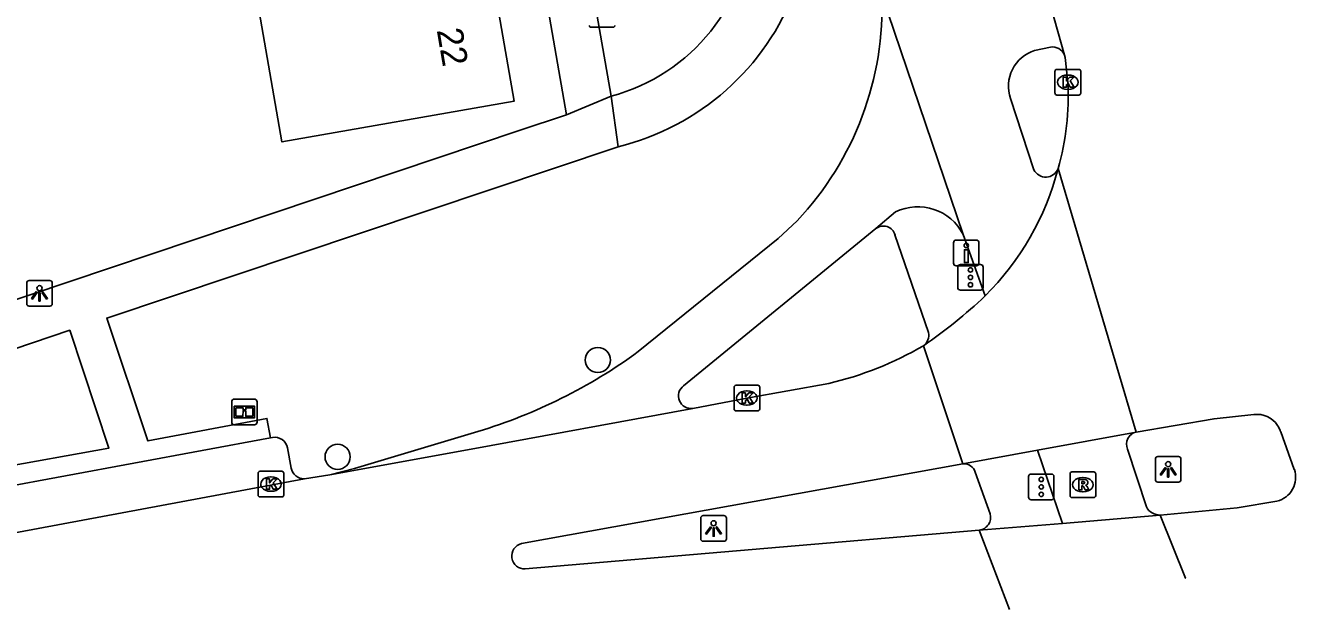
# Model space of a CAD drawing. Extents: x 160158 to 160921, y 381517 to 382041.
# Drawn here: x 160482.63 to 160532.12, y 381526.49 to 381549.26 of the extents above; entities that cross this region are included whole.
import ezdxf

# ---------------------------------------------------------------- set-up
doc = ezdxf.new("R2010")
doc.units = 0
for name, color, linetype in [('IMGEO_Boom', 7, 'Continuous'), ('IMGEO_Drukknoppaal', 7, 'Continuous'), ('IMGEO_Fietspad_gesloten', 7, 'Continuous'), ('IMGEO_Informatiebord', 7, 'Continuous'), ('IMGEO_Kolk', 7, 'Continuous'), ('IMGEO_Lichtpunt', 7, 'Continuous'), ('IMGEO_Pand', 7, 'Continuous'), ('IMGEO_Pand_nummerreeks', 7, 'Continuous'), ('IMGEO_Parkeervlak_open', 7, 'Continuous'), ('IMGEO_Rijbaan_lokaal_gesloten', 7, 'Continuous'), ('IMGEO_Rijbaan_regionaal_gesloten', 7, 'Continuous'), ('IMGEO_Rioolput', 7, 'Continuous'), ('IMGEO_Verkeersregelinstallatiepaal', 7, 'Continuous'), ('IMGEO_Voetpad_open', 7, 'Continuous')]:
    doc.layers.add(name, color=color, linetype=linetype)

msp = doc.modelspace()

# ---------------------------------------------------------------- linework, layer by layer
at = {"layer": 'IMGEO_Boom'}
for centre in [(160504.935, 381536.218), (160494.795, 381532.443)]:
    msp.add_circle(centre, 0.489, dxfattribs=at)
at = {"layer": 'IMGEO_Drukknoppaal'}
for p, q in [((160518.794, 381539.992), (160518.794, 381540.792)), ((160518.794, 381540.792), (160518.794, 381539.992)), ((160518.894, 381540.892), (160519.684, 381540.892)), ((160519.684, 381540.892), (160518.894, 381540.892)), ((160519.784, 381540.792), (160519.784, 381539.992)), ((160519.784, 381539.992), (160519.784, 381540.792)), ((160519.684, 381539.892), (160518.894, 381539.892)), ((160518.894, 381539.892), (160519.684, 381539.892))]:
    msp.add_line(p, q, dxfattribs=at)
msp.add_lwpolyline([(160519.364, 381540.517), (160519.364, 381540.017), (160519.214, 381540.017), (160519.214, 381540.517), (160519.364, 381540.517)], dxfattribs=at)
msp.add_circle((160519.289, 381540.682), 0.085, dxfattribs=at)
for centre, start, end in [((160518.894, 381540.792), 90, 180), ((160518.894, 381540.792), 90, 180), ((160519.684, 381540.792), 0, 90), ((160519.684, 381540.792), 360, 90), ((160518.894, 381539.992), 180, 270), ((160518.894, 381539.992), 180, 270), ((160519.684, 381539.992), 270, 0), ((160519.684, 381539.992), 270, 0)]:
    msp.add_arc(centre, 0.1, start, end, dxfattribs=at)
at = {"layer": 'IMGEO_Fietspad_gesloten'}
for points in [[(160515.994, 381550.461), (160519.169, 381541.105)], [(160521.952, 381548.285), (160522.568, 381548.415)], [(160521.927, 381543.633), (160521.008, 381546.411)], [(160515.762, 381541.343), (160516.531, 381541.99)], [(160512.701, 381541.648), (160511.966, 381540.956), (160506.509, 381536.545)], [(160508.278, 381535.212), (160515.762, 381541.343)], [(160519.169, 381541.105), (160520.02, 381538.714)], [(160500.264, 381533.433), (160495.449, 381531.994), (160494.487, 381531.742)], [(160522.061, 381532.706), (160523.041, 381529.844)], [(160525.573, 381532.737), (160526.311, 381530.488)]]:
    msp.add_lwpolyline(points, dxfattribs=at)
for centre, radius, start, end in [((160503.878, 381549.967), 12.126, 316.6864, 2.3369), ((160522.652, 381547.922), 0.5, 21.5779, 99.6769), ((160522.404, 381546.882), 1.474, 107.8788, 198.6492), ((160522.387, 381543.858), 0.512, 206.0086, 339.4729), ((160517.403, 381540.215), 1.977, 26.7399, 116.1688), ((160494.294, 381553.235), 20.682, 286.7768, 306.1991), ((160508.562, 381534.816), 0.488, 125.6155, 279.0857), ((160526.027, 381532.931), 0.494, 103.4475, 203.1507), ((160526.835, 381530.767), 0.594, 207.982, 271.1336)]:
    msp.add_arc(centre, radius, start, end, dxfattribs=at)
at = {"layer": 'IMGEO_Informatiebord'}
for p, q in [((160490.668, 381533.793), (160490.668, 381534.593)), ((160490.668, 381534.593), (160490.668, 381533.793)), ((160490.768, 381534.693), (160491.558, 381534.693)), ((160491.558, 381534.693), (160490.768, 381534.693)), ((160491.658, 381534.593), (160491.658, 381533.793)), ((160491.658, 381533.793), (160491.658, 381534.593)), ((160491.558, 381533.693), (160490.768, 381533.693)), ((160490.768, 381533.693), (160491.558, 381533.693))]:
    msp.add_line(p, q, dxfattribs=at)
for points in [[(160490.769, 381534.425), (160491.557, 381534.425), (160491.557, 381533.961), (160490.769, 381533.961), (160490.769, 381534.425)], [(160490.834, 381534.36), (160490.834, 381534.026), (160491.109, 381534.026), (160491.11, 381534.239), (160491.214, 381534.24), (160491.215, 381534.026), (160491.492, 381534.026), (160491.492, 381534.36), (160491.216, 381534.36), (160491.216, 381534.28), (160491.11, 381534.28), (160491.11, 381534.36), (160490.834, 381534.36)]]:
    msp.add_lwpolyline(points, dxfattribs=at)
for centre, start, end in [((160490.768, 381534.593), 90, 180), ((160490.768, 381534.593), 90, 180), ((160491.558, 381534.593), 0, 90), ((160491.558, 381534.593), 360, 90), ((160490.768, 381533.793), 180, 270), ((160490.768, 381533.793), 180, 270), ((160491.558, 381533.793), 270, 0), ((160491.558, 381533.793), 270, 0)]:
    msp.add_arc(centre, 0.1, start, end, dxfattribs=at)
at = {"layer": 'IMGEO_Kolk'}
for p, q in [((160522.746, 381546.622), (160522.746, 381547.474)), ((160522.821, 381547.548), (160523.673, 381547.548)), ((160523.747, 381547.474), (160523.747, 381546.622)), ((160523.234, 381547.328), (160523.259, 381547.328)), ((160523.673, 381546.548), (160522.821, 381546.548)), ((160523.257, 381546.768), (160523.232, 381546.768)), ((160510.243, 381534.31), (160510.243, 381535.162)), ((160510.318, 381535.236), (160511.17, 381535.236)), ((160510.731, 381535.016), (160510.756, 381535.016)), ((160511.244, 381535.162), (160511.244, 381534.31)), ((160511.17, 381534.236), (160510.318, 381534.236)), ((160510.754, 381534.456), (160510.729, 381534.456)), ((160491.698, 381530.954), (160491.698, 381531.806)), ((160491.773, 381531.88), (160492.625, 381531.88)), ((160492.186, 381531.66), (160492.211, 381531.66)), ((160492.699, 381531.806), (160492.699, 381530.954)), ((160492.209, 381531.1), (160492.184, 381531.1)), ((160492.625, 381530.88), (160491.773, 381530.88))]:
    msp.add_line(p, q, dxfattribs=at)
for points in [[(160522.746, 381546.622), (160522.746, 381547.474)], [(160522.821, 381547.548), (160523.673, 381547.548)], [(160523.747, 381547.474), (160523.747, 381546.622)], [(160523.067, 381547.248), (160523.19, 381547.248), (160523.19, 381547.097), (160523.32, 381547.248), (160523.484, 381547.248), (160523.338, 381547.097), (160523.491, 381546.848), (160523.339, 381546.848), (160523.254, 381547.012), (160523.19, 381546.945), (160523.19, 381546.848), (160523.067, 381546.848), (160523.067, 381547.248)], [(160523.673, 381546.548), (160522.821, 381546.548)], [(160510.243, 381534.31), (160510.243, 381535.162)], [(160510.318, 381535.236), (160511.17, 381535.236)], [(160511.244, 381535.162), (160511.244, 381534.31)], [(160510.564, 381534.936), (160510.687, 381534.936), (160510.687, 381534.785), (160510.817, 381534.936), (160510.981, 381534.936), (160510.835, 381534.785), (160510.988, 381534.536), (160510.836, 381534.536), (160510.751, 381534.7), (160510.687, 381534.633), (160510.687, 381534.536), (160510.564, 381534.536), (160510.564, 381534.936)], [(160511.17, 381534.236), (160510.318, 381534.236)], [(160491.698, 381530.954), (160491.698, 381531.806)], [(160491.773, 381531.88), (160492.625, 381531.88)], [(160492.019, 381531.58), (160492.142, 381531.58), (160492.142, 381531.429), (160492.272, 381531.58), (160492.436, 381531.58), (160492.29, 381531.429), (160492.443, 381531.18), (160492.291, 381531.18), (160492.206, 381531.344), (160492.142, 381531.277), (160492.142, 381531.18), (160492.019, 381531.18), (160492.019, 381531.58)], [(160492.699, 381531.806), (160492.699, 381530.954)], [(160492.625, 381530.88), (160491.773, 381530.88)]]:
    msp.add_lwpolyline(points, dxfattribs=at)
for centre, start, end in [((160522.823, 381547.472), 91.552, 178.448), ((160522.823, 381547.472), 91.552, 178.448), ((160523.671, 381547.472), 1.552, 88.448), ((160523.671, 381547.472), 1.552, 88.448), ((160522.823, 381546.624), 181.552, 268.448), ((160522.823, 381546.624), 181.552, 268.448), ((160523.671, 381546.624), 271.552, 358.448), ((160523.671, 381546.624), 271.552, 358.448), ((160510.32, 381535.16), 91.552, 178.448), ((160510.32, 381535.16), 91.552, 178.448), ((160511.168, 381535.16), 1.552, 88.448), ((160511.168, 381535.16), 1.552, 88.448), ((160510.32, 381534.312), 181.552, 268.448), ((160510.32, 381534.312), 181.552, 268.448), ((160511.168, 381534.312), 271.552, 358.448), ((160511.168, 381534.312), 271.552, 358.448), ((160491.775, 381531.804), 91.552, 178.448), ((160491.775, 381531.804), 91.552, 178.448), ((160492.623, 381531.804), 1.552, 88.448), ((160492.623, 381531.804), 1.552, 88.448), ((160491.775, 381530.956), 181.552, 268.448), ((160491.775, 381530.956), 181.552, 268.448), ((160492.623, 381530.956), 271.552, 358.448), ((160492.623, 381530.956), 271.552, 358.448)]:
    msp.add_arc(centre, 0.0765, start, end, dxfattribs=at)
for centre, major_axis, ratio, start_param, end_param in [((160523.233, 381547.048), (-0.387, 0.002), 0.722429, 4.712389, 7.853982), ((160523.258, 381547.048), (-0.39, 0.002), 0.717154, 1.570796, 4.712389), ((160510.73, 381534.736), (-0.387, 0.002), 0.722429, 4.712389, 7.853982), ((160510.755, 381534.736), (-0.39, 0.002), 0.717154, 1.570796, 4.712389), ((160492.185, 381531.38), (-0.387, 0.002), 0.722429, 4.712389, 7.853982), ((160492.21, 381531.38), (-0.39, 0.002), 0.717154, 1.570796, 4.712389)]:
    msp.add_ellipse(centre, major_axis=major_axis, ratio=ratio, start_param=start_param, end_param=end_param, dxfattribs=at)
at = {"layer": 'IMGEO_Lichtpunt'}
for p, q in [((160482.683, 381539.219), (160482.683, 381538.412)), ((160482.683, 381539.219), (160482.683, 381538.412)), ((160483.585, 381539.314), (160482.777, 381539.314)), ((160483.585, 381539.314), (160482.777, 381539.314)), ((160483.679, 381538.412), (160483.679, 381539.219)), ((160483.679, 381538.412), (160483.679, 381539.219)), ((160482.777, 381538.318), (160483.585, 381538.318)), ((160482.777, 381538.318), (160483.585, 381538.318)), ((160526.658, 381532.36), (160526.658, 381531.553)), ((160526.658, 381532.36), (160526.658, 381531.553)), ((160527.56, 381532.455), (160526.752, 381532.455)), ((160527.56, 381532.455), (160526.752, 381532.455)), ((160527.654, 381531.553), (160527.654, 381532.36)), ((160527.654, 381531.553), (160527.654, 381532.36)), ((160526.752, 381531.459), (160527.56, 381531.459)), ((160526.752, 381531.459), (160527.56, 381531.459)), ((160509.848, 381530.151), (160509.04, 381530.151)), ((160509.848, 381530.151), (160509.04, 381530.151)), ((160508.946, 381530.056), (160508.946, 381529.249)), ((160508.946, 381530.056), (160508.946, 381529.249)), ((160509.942, 381529.249), (160509.942, 381530.056)), ((160509.942, 381529.249), (160509.942, 381530.056)), ((160509.04, 381529.155), (160509.848, 381529.155)), ((160509.04, 381529.155), (160509.848, 381529.155))]:
    msp.add_line(p, q, dxfattribs=at)
for points in [[(160483.057, 381538.883), (160483.096, 381538.855), (160482.908, 381538.593), (160482.87, 381538.62), (160483.057, 381538.883)], [(160483.159, 381538.835), (160483.206, 381538.835), (160483.206, 381538.513), (160483.159, 381538.513), (160483.159, 381538.835)], [(160483.269, 381538.855), (160483.307, 381538.882), (160483.494, 381538.62), (160483.455, 381538.592), (160483.269, 381538.855)], [(160527.032, 381532.024), (160527.071, 381531.996), (160526.883, 381531.734), (160526.845, 381531.761), (160527.032, 381532.024)], [(160527.134, 381531.976), (160527.181, 381531.976), (160527.181, 381531.654), (160527.134, 381531.654), (160527.134, 381531.976)], [(160527.244, 381531.996), (160527.282, 381532.023), (160527.469, 381531.761), (160527.43, 381531.733), (160527.244, 381531.996)], [(160509.32, 381529.72), (160509.359, 381529.692), (160509.171, 381529.43), (160509.133, 381529.457), (160509.32, 381529.72)], [(160509.422, 381529.672), (160509.469, 381529.672), (160509.469, 381529.35), (160509.422, 381529.35), (160509.422, 381529.672)], [(160509.532, 381529.692), (160509.57, 381529.719), (160509.757, 381529.457), (160509.718, 381529.429), (160509.532, 381529.692)]]:
    msp.add_lwpolyline(points, dxfattribs=at)
for centre in [(160483.182, 381539.017), (160527.157, 381532.158), (160509.445, 381529.854)]:
    msp.add_circle(centre, 0.0994, dxfattribs=at)
for centre, start, end in [((160482.777, 381539.219), 90, 180), ((160482.777, 381539.219), 90, 180), ((160483.585, 381539.219), 0, 90), ((160483.585, 381539.219), 0, 90), ((160482.777, 381538.412), 180, 270), ((160482.777, 381538.412), 180, 270), ((160483.585, 381538.412), 270, 0), ((160483.585, 381538.412), 270, 360), ((160526.752, 381532.36), 90, 180), ((160526.752, 381532.36), 90, 180), ((160527.56, 381532.36), 0, 90), ((160527.56, 381532.36), 0, 90), ((160526.752, 381531.553), 180, 270), ((160526.752, 381531.553), 180, 270), ((160527.56, 381531.553), 270, 0), ((160527.56, 381531.553), 270, 360), ((160509.04, 381530.056), 90, 180), ((160509.04, 381530.056), 90, 180), ((160509.848, 381530.056), 0, 90), ((160509.848, 381530.056), 0, 90), ((160509.04, 381529.249), 180, 270), ((160509.04, 381529.249), 180, 270), ((160509.848, 381529.249), 270, 0), ((160509.848, 381529.249), 270, 360)]:
    msp.add_arc(centre, 0.0946, start, end, dxfattribs=at)
at = {"layer": 'IMGEO_Pand'}
msp.add_lwpolyline([(160491.738, 381549.803), (160492.623, 381544.717), (160501.674, 381546.306), (160500.787, 381551.392)], dxfattribs=at)
at = {"layer": 'IMGEO_Parkeervlak_open'}
for points in [[(160492.255, 381533.202), (160492.18, 381533.188)], [(160492.992, 381532.008), (160492.843, 381532.79)]]:
    msp.add_lwpolyline(points, dxfattribs=at)
for centre, radius, start, end in [((160492.339, 381532.697), 0.512, 10.4903, 99.4734), ((160493.485, 381532.086), 0.499, 188.9955, 271.7047)]:
    msp.add_arc(centre, radius, start, end, dxfattribs=at)
at = {"layer": 'IMGEO_Rijbaan_lokaal_gesloten'}
for points in [[(160519.16, 381532.168), (160517.621, 381536.772)], [(160513.931, 381535.305), (160510.743, 381534.735), (160508.639, 381534.334)], [(160508.639, 381534.334), (160500, 381532.746), (160494.487, 381531.742)], [(160522.061, 381532.706), (160525.912, 381533.411)], [(160519.16, 381532.168), (160522.061, 381532.706)], [(160501.964, 381529.06), (160519.16, 381532.168)], [(160493.5, 381531.587), (160480.817, 381529.226)], [(160494.487, 381531.742), (160493.5, 381531.587)], [(160526.847, 381530.173), (160523.041, 381529.844)], [(160519.788, 381529.587), (160502.108, 381528.076)], [(160523.041, 381529.844), (160519.788, 381529.587)], [(160519.788, 381529.587), (160520.971, 381526.488)]]:
    msp.add_lwpolyline(points, dxfattribs=at)
for centre, radius, start, end in [((160512.35, 381546.412), 10.867, 314.8982, 345.4307), ((160506.215, 381553.315), 20.095, 304.5857, 313.3949), ((160510.917, 381548.26), 13.301, 283.0961, 300.2655), ((160502.076, 381528.574), 0.499, 102.9341, 273.7172)]:
    msp.add_arc(centre, radius, start, end, dxfattribs=at)
at = {"layer": 'IMGEO_Rijbaan_regionaal_gesloten'}
for points in [[(160522.336, 381550.885), (160523.117, 381548.106)], [(160523.117, 381548.106), (160523.145, 381548.007), (160523.249, 381547.047)], [(160522.867, 381543.678), (160525.912, 381533.411)], [(160525.912, 381533.411), (160528.942, 381533.927), (160530.497, 381534.094)], [(160531.539, 381533.419), (160532.071, 381531.95)], [(160531.394, 381530.711), (160529.841, 381530.449), (160526.847, 381530.173)], [(160526.847, 381530.173), (160527.83, 381527.708), (160527.83, 381527.708)]]:
    msp.add_lwpolyline(points, dxfattribs=at)
for centre, radius, start, end in [((160513.141, 381546.487), 10.124, 343.891, 3.1711), ((160530.608, 381533.123), 0.977, 34.0999, 96.5158), ((160530.586, 381533.113), 1, 17.7884, 33.8774), ((160531.156, 381531.646), 0.965, 284.3107, 18.3841)]:
    msp.add_arc(centre, radius, start, end, dxfattribs=at)
at = {"layer": 'IMGEO_Rioolput'}
for p, q in [((160505.525, 381549.188), (160504.673, 381549.188)), ((160523.332, 381530.931), (160523.332, 381531.783)), ((160523.407, 381531.857), (160524.259, 381531.857)), ((160523.82, 381531.637), (160523.845, 381531.637)), ((160524.333, 381531.783), (160524.333, 381530.931)), ((160523.843, 381531.077), (160523.818, 381531.077)), ((160524.259, 381530.857), (160523.407, 381530.857))]:
    msp.add_line(p, q, dxfattribs=at)
for points in [[(160505.525, 381549.188), (160504.673, 381549.188)], [(160523.332, 381530.931), (160523.332, 381531.783)], [(160523.407, 381531.857), (160524.259, 381531.857)], [(160523.921, 381531.555), (160523.669, 381531.557), (160523.669, 381531.157)], [(160524.333, 381531.783), (160524.333, 381530.931)], [(160523.669, 381531.157), (160523.793, 381531.157), (160523.793, 381531.319), (160523.804, 381531.319)], [(160523.847, 381531.476), (160523.793, 381531.476), (160523.793, 381531.395)], [(160523.793, 381531.395), (160523.845, 381531.395)], [(160523.851, 381531.29), (160523.922, 381531.157), (160524.062, 381531.157), (160523.997, 381531.283)], [(160524.259, 381530.857), (160523.407, 381530.857)]]:
    msp.add_lwpolyline(points, dxfattribs=at)
for centre, radius, start, end in [((160504.675, 381549.264), 0.0765, 181.552, 268.448), ((160504.675, 381549.264), 0.0765, 181.552, 268.448), ((160505.523, 381549.264), 0.0765, 271.552, 358.448), ((160505.523, 381549.264), 0.0765, 271.552, 358.448), ((160523.409, 381531.781), 0.0765, 91.552, 178.448), ((160523.409, 381531.781), 0.0765, 91.552, 178.448), ((160523.92, 381531.445), 0.109, 350.3612, 89.416), ((160524.257, 381531.781), 0.0765, 1.552, 88.448), ((160524.257, 381531.781), 0.0765, 1.552, 88.448), ((160523.803, 381531.266), 0.0533, 26.0293, 88.6989), ((160523.829, 381531.584), 0.19, 274.7715, 282.9687), ((160523.853, 381531.38), 0.0964, 77.0061, 93.1865), ((160523.867, 381531.437), 0.0378, 276.6634, 79.6772), ((160523.918, 381531.445), 0.112, 277.5842, 350.9817), ((160523.902, 381531.23), 0.108, 29.5134, 73.7905), ((160523.409, 381530.933), 0.0765, 181.552, 268.448), ((160523.409, 381530.933), 0.0765, 181.552, 268.448), ((160524.257, 381530.933), 0.0765, 271.552, 358.448), ((160524.257, 381530.933), 0.0765, 271.552, 358.448)]:
    msp.add_arc(centre, radius, start, end, dxfattribs=at)
for centre, major_axis, ratio, start_param, end_param in [((160523.819, 381531.357), (-0.387, 0.002), 0.722429, 4.712389, 7.853982), ((160523.844, 381531.357), (-0.39, 0.002), 0.717154, 1.570796, 4.712389)]:
    msp.add_ellipse(centre, major_axis=major_axis, ratio=ratio, start_param=start_param, end_param=end_param, dxfattribs=at)
at = {"layer": 'IMGEO_Verkeersregelinstallatiepaal'}
for p, q in [((160518.958, 381539.04), (160518.958, 381539.84)), ((160518.958, 381539.84), (160518.958, 381539.04)), ((160519.058, 381539.94), (160519.848, 381539.94)), ((160519.848, 381539.94), (160519.058, 381539.94)), ((160519.948, 381539.84), (160519.948, 381539.04)), ((160519.948, 381539.04), (160519.948, 381539.84)), ((160519.848, 381538.94), (160519.058, 381538.94)), ((160519.058, 381538.94), (160519.848, 381538.94)), ((160521.715, 381530.871), (160521.715, 381531.671)), ((160521.715, 381531.671), (160521.715, 381530.871)), ((160521.815, 381531.771), (160522.605, 381531.771)), ((160522.605, 381531.771), (160521.815, 381531.771)), ((160522.705, 381531.671), (160522.705, 381530.871)), ((160522.705, 381530.871), (160522.705, 381531.671)), ((160522.605, 381530.771), (160521.815, 381530.771)), ((160521.815, 381530.771), (160522.605, 381530.771))]:
    msp.add_line(p, q, dxfattribs=at)
for centre in [(160519.453, 381539.73), (160519.453, 381539.44), (160519.453, 381539.15), (160522.21, 381531.561), (160522.21, 381531.271), (160522.21, 381530.981)]:
    msp.add_circle(centre, 0.085, dxfattribs=at)
for centre, start, end in [((160519.058, 381539.84), 90, 180), ((160519.058, 381539.84), 90, 180), ((160519.848, 381539.84), 0, 90), ((160519.848, 381539.84), 360, 90), ((160519.058, 381539.04), 180, 270), ((160519.058, 381539.04), 180, 270), ((160519.848, 381539.04), 270, 0), ((160519.848, 381539.04), 270, 0), ((160521.815, 381531.671), 90, 180), ((160521.815, 381531.671), 90, 180), ((160522.605, 381531.671), 0, 90), ((160522.605, 381531.671), 360, 90), ((160521.815, 381530.871), 180, 270), ((160521.815, 381530.871), 180, 270), ((160522.605, 381530.871), 270, 0), ((160522.605, 381530.871), 270, 0)]:
    msp.add_arc(centre, 0.1, start, end, dxfattribs=at)
at = {"layer": 'IMGEO_Voetpad_open'}
for points in [[(160502.36, 381584.773), (160498.863, 381584.173), (160505.451, 381546.503)], [(160503.713, 381545.771), (160497.086, 381583.845), (160473.981, 381579.836)], [(160505.451, 381546.503), (160503.713, 381545.771)], [(160505.451, 381546.503), (160505.721, 381544.532)], [(160481.182, 381538.213), (160501.869, 381545.165), (160503.713, 381545.771)], [(160505.721, 381544.532), (160485.804, 381537.855), (160487.403, 381533.066), (160492.04, 381533.938), (160492.18, 381533.188)], [(160517.815, 381537.292), (160516.512, 381541.091)], [(160481.523, 381531.215), (160481.386, 381531.97), (160485.883, 381532.785), (160484.361, 381537.378), (160474.854, 381534.159)], [(160492.18, 381533.188), (160481.523, 381531.215)], [(160520.219, 381530.222), (160519.639, 381531.846)]]:
    msp.add_lwpolyline(points, dxfattribs=at)
for centre, radius, start, end in [((160503.545, 381553.664), 7.41, 284.9017, 357.7888), ((160503.382, 381554.124), 9.873, 283.7064, 339.4721), ((160516.052, 381540.963), 0.478, 15.5111, 127.3442), ((160517.305, 381537.186), 0.521, 307.3564, 11.7248), ((160519.207, 381531.721), 0.45, 16.1588, 96.0205), ((160519.735, 381530.087), 0.503, 276.0823, 15.585)]:
    msp.add_arc(centre, radius, start, end, dxfattribs=at)

# ---------------------------------------------------------------- texts
at = {"layer": 'IMGEO_Pand_nummerreeks'}
msp.add_text('22', height=1, rotation=279.6942, dxfattribs=at).set_placement((160498.656, 381549.078))

doc.saveas('drawing.dxf')
